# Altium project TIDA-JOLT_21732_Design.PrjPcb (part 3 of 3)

## Sheet JOLT_21732_Supply_Bias.SchDoc
size 431 x 279 mm; Date: Not shown in title block; ApprovedBy: Not shown in title block; CheckedBy: Not shown in title block; Author: Not shown in title block; CompanyName: Not shown in title block; DrawnBy: X.Gong; Engineer: Not shown in title block; Organization: Not shown in title block; Address1: Not shown in title block; Address2: Not shown in title block; Address3: Not shown in title block; Address4: Not shown in title block; DocumentNumber: 4; Revision: Use project parameter SCH_Rev; SheetNumber: 4; SheetTotal: 5; PageSetup: Record=PageOptions¦CenterHorizontal=True¦CenterVertical=True¦PrintScale=1.00¦XCorrection=1.00¦YCorrection=1.00¦PrintKind=0¦BorderSize=5000000¦LeftOffset=0¦BottomOffset=0¦Orientation=2¦PaperLength=1000¦PaperWidth=1000¦Scale=100¦PaperSource=15¦PrintQuality=600¦MediaType=1¦DitherType=10¦PaperKind=Letter¦PrintScaleMode=1
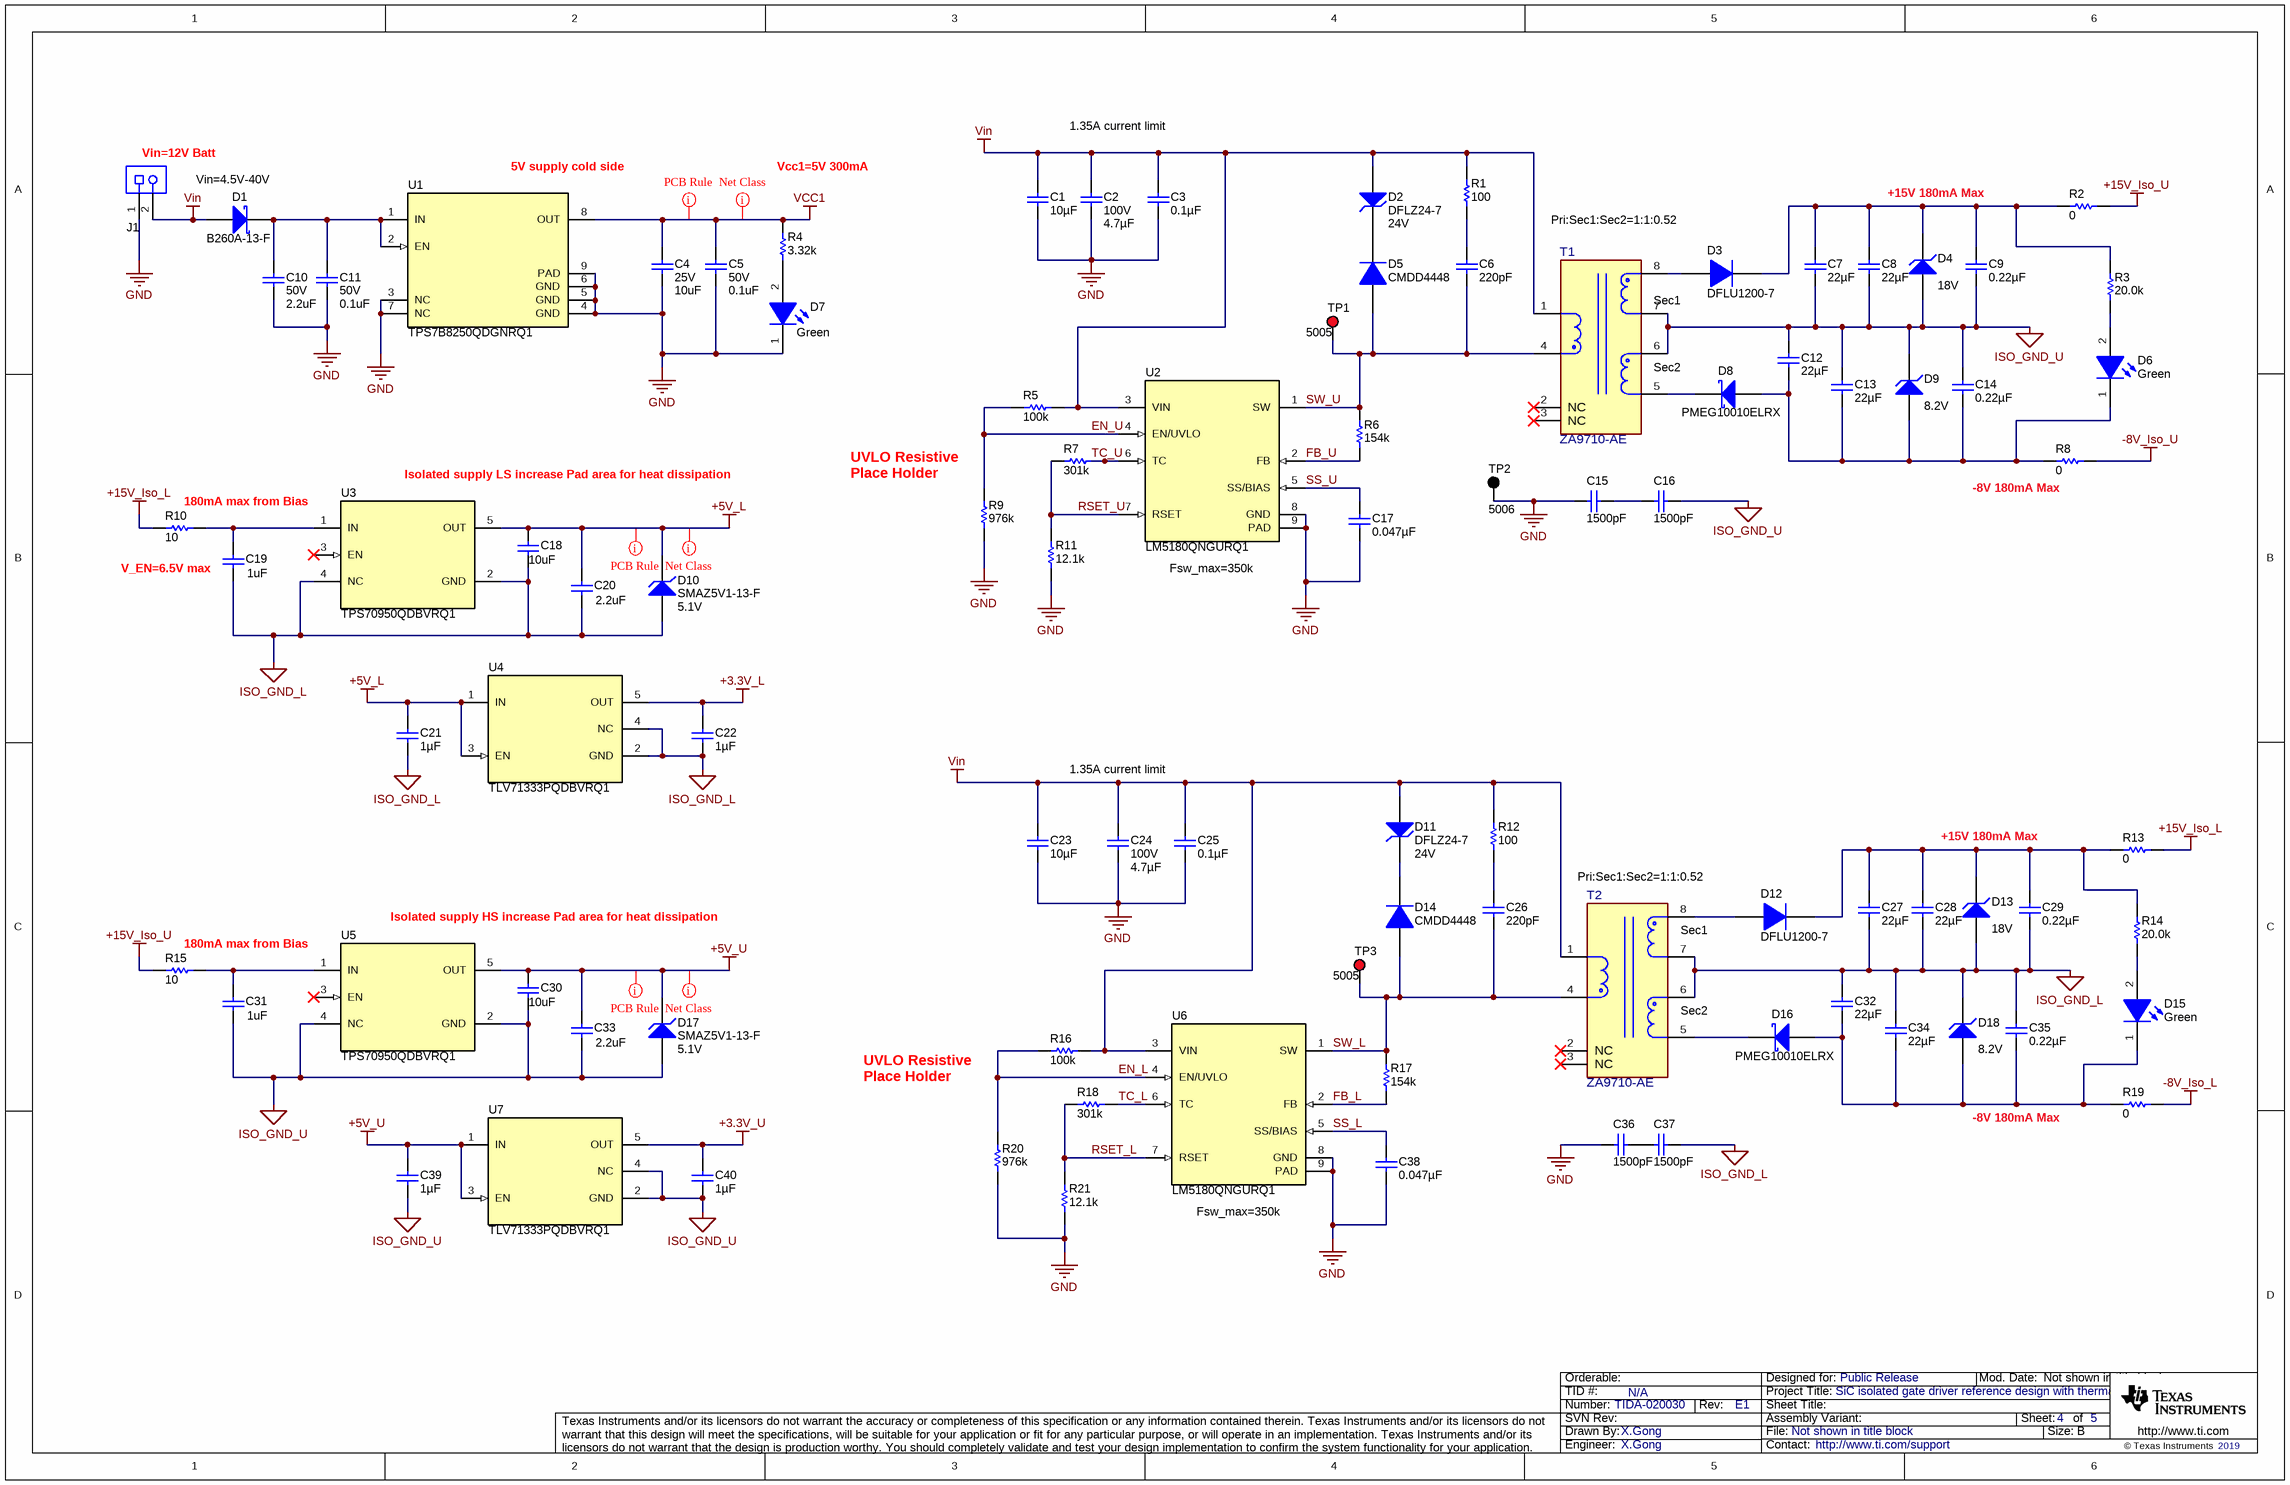
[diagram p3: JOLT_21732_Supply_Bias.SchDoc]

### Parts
C1  ValueDisplayed: 10µF  [2220_250]  (hidden comment: C5750X7S2A106K230KB)
C2  VDC_V: 100V  ValueDisplayed: 4.7µF  [1210_220]  (hidden comment: GCM32DC72A475KE02L)
C3  ValueDisplayed: 0.1µF  [0805_HV]  (hidden comment: GRM21BR72A104KAC4L)
C4  VDC_V: 25V  ValueDisplayed: 10uF  [1206_180]  (hidden comment: GRM31CR71E106KA12L)
C5  VDC_V: 50V  ValueDisplayed: 0.1uF  [0805_HV]  (hidden comment: GRM21BR71H104KA01L)
C6  ValueDisplayed: 220pF  [0603]  (hidden comment: GRM1885C2A221JA01D)
C7  ValueDisplayed: 22µF  [0805_HV]  (hidden comment: GRM21BR61E226ME44L)
C8  ValueDisplayed: 22µF  [0805_HV]  (hidden comment: GRM21BR61E226ME44L)
C9  ValueDisplayed: 0.22µF  [0805_HV]  (hidden comment: GRM21BR71H224KA01L)
C10  VDC_V: 50V  ValueDisplayed: 2.2uF  [1206_180]  (hidden comment: GRM31CR71H225KA88L)
C11  VDC_V: 50V  ValueDisplayed: 0.1uF  [0805_HV]  (hidden comment: GRM21BR71H104KA01L)
C12  ValueDisplayed: 22µF  [0805_HV]  (hidden comment: GRM21BR61E226ME44L)
C13  ValueDisplayed: 22µF  [0805_HV]  (hidden comment: GRM21BR61E226ME44L)
C14  ValueDisplayed: 0.22µF  [0805_HV]  (hidden comment: GRM21BR71H224KA01L)
C15  ValueDisplayed: 1500pF  [KY_700x500x1000]  (hidden comment: DE2E3KY152MN3AM02F)
C16  ValueDisplayed: 1500pF  [KY_700x500x1000]  (hidden comment: DE2E3KY152MN3AM02F)
C17  ValueDisplayed: 0.047µF  [0603]  (hidden comment: GRM188R71C473KA01D)
C18  ValueDisplayed: 10uF  [0805_HV]  (hidden comment: C2012X5R1E106K125AB)
C19  ValueDisplayed: 1uF  [0603]  (hidden comment: UMK107AB7105KA-T)
C20  ValueDisplayed: 2.2uF  [1206]  (hidden comment: C1206C225K4RACTU)
C21  ValueDisplayed: 1µF  [0603]  (hidden comment: GRM188R71E105KA12D)
C22  ValueDisplayed: 1µF  [0603]  (hidden comment: GRM188R71E105KA12D)
C23  ValueDisplayed: 10µF  [2220_250]  (hidden comment: C5750X7S2A106K230KB)
C24  VDC_V: 100V  ValueDisplayed: 4.7µF  [1210_220]  (hidden comment: GCM32DC72A475KE02L)
C25  ValueDisplayed: 0.1µF  [0805_HV]  (hidden comment: GRM21BR72A104KAC4L)
C26  ValueDisplayed: 220pF  [0603]  (hidden comment: GRM1885C2A221JA01D)
C27  ValueDisplayed: 22µF  [0805_HV]  (hidden comment: GRM21BR61E226ME44L)
C28  ValueDisplayed: 22µF  [0805_HV]  (hidden comment: GRM21BR61E226ME44L)
C29  ValueDisplayed: 0.22µF  [0805_HV]  (hidden comment: GRM21BR71H224KA01L)
C30  ValueDisplayed: 10uF  [0805_HV]  (hidden comment: C2012X5R1E106K125AB)
C31  ValueDisplayed: 1uF  [0603]  (hidden comment: UMK107AB7105KA-T)
C32  ValueDisplayed: 22µF  [0805_HV]  (hidden comment: GRM21BR61E226ME44L)
C33  ValueDisplayed: 2.2uF  [1206]  (hidden comment: C1206C225K4RACTU)
C34  ValueDisplayed: 22µF  [0805_HV]  (hidden comment: GRM21BR61E226ME44L)
C35  ValueDisplayed: 0.22µF  [0805_HV]  (hidden comment: GRM21BR71H224KA01L)
C36  ValueDisplayed: 1500pF  [KY_700x500x1000]  (hidden comment: DE2E3KY152MN3AM02F)
C37  ValueDisplayed: 1500pF  [KY_700x500x1000]  (hidden comment: DE2E3KY152MN3AM02F)
C38  ValueDisplayed: 0.047µF  [0603]  (hidden comment: GRM188R71C473KA01D)
C39  ValueDisplayed: 1µF  [0603]  (hidden comment: GRM188R71E105KA12D)
C40  ValueDisplayed: 1µF  [0603]  (hidden comment: GRM188R71E105KA12D)
D1  B260A-13-F  [SMA]
D2  DFLZ24-7  value 24V  [PowerDI123]
D3  DFLU1200-7  [PowerDI123]
D4  value 18V  [SOD-123]  (hidden comment: BZT52C18-7-F)
D5  CMDD4448  [SOD-323]
D6  value Green  [WL-SMCW_GREEN]  (hidden comment: 150060GS75000)
D7  value Green  [WL-SMCW_GREEN]  (hidden comment: 150060GS75000)
D8  PMEG10010ELRX  [SOD-123W]
D9  value 8.2V  [SOD-123]  (hidden comment: BZT52C8V2-7-F)
D10  SMAZ5V1-13-F  value 5.1V  [SMA]
D11  DFLZ24-7  value 24V  [PowerDI123]
D12  DFLU1200-7  [PowerDI123]
D13  value 18V  [SOD-123]  (hidden comment: BZT52C18-7-F)
D14  CMDD4448  [SOD-323]
D15  value Green  [WL-SMCW_GREEN]  (hidden comment: 150060GS75000)
D16  PMEG10010ELRX  [SOD-123W]
D17  SMAZ5V1-13-F  value 5.1V  [SMA]
D18  value 8.2V  [SOD-123]  (hidden comment: BZT52C8V2-7-F)
J1  OSTVN02A150  [On-Shore_OSTVN02A150]  (value not drawn)
R1  ValueDisplayed: 100  [0805_HV]  (hidden comment: CRCW0805100RFKEA)
R2  ValueDisplayed: 0  [0603]  (hidden comment: ERJ-3GEY0R00V)
R3  ValueDisplayed: 20.0k  [0805_HV]  (hidden comment: CRCW080520K0FKEA)
R4  ValueDisplayed: 3.32k  [0402]  (hidden comment: CRCW04023K32FKED)
R5  ValueDisplayed: 100k  [0805_HV]  (hidden comment: CRCW0805100KFKEA)
R6  ValueDisplayed: 154k  [0603]  (hidden comment: CRCW0603154KFKEA)
R7  ValueDisplayed: 301k  [0603]  (hidden comment: CRCW0603301KFKEA)
R8  ValueDisplayed: 0  [0603]  (hidden comment: ERJ-3GEY0R00V)
R9  ValueDisplayed: 976k  [0603]  (hidden comment: CRCW0603976KFKEA)
R10  ValueDisplayed: 10  [0805_HV]  (hidden comment: CRCW080510R0JNEA)
R11  ValueDisplayed: 12.1k  [0805_HV]  (hidden comment: CRCW080512K1FKEA)
R12  ValueDisplayed: 100  [0805_HV]  (hidden comment: CRCW0805100RFKEA)
R13  ValueDisplayed: 0  [0603]  (hidden comment: ERJ-3GEY0R00V)
R14  ValueDisplayed: 20.0k  [0805_HV]  (hidden comment: CRCW080520K0FKEA)
R15  ValueDisplayed: 10  [0805_HV]  (hidden comment: CRCW080510R0JNEA)
R16  ValueDisplayed: 100k  [0805_HV]  (hidden comment: CRCW0805100KFKEA)
R17  ValueDisplayed: 154k  [0603]  (hidden comment: CRCW0603154KFKEA)
R18  ValueDisplayed: 301k  [0603]  (hidden comment: CRCW0603301KFKEA)
R19  ValueDisplayed: 0  [0603]  (hidden comment: ERJ-3GEY0R00V)
R20  ValueDisplayed: 976k  [0603]  (hidden comment: CRCW0603976KFKEA)
R21  ValueDisplayed: 12.1k  [0805_HV]  (hidden comment: CRCW080512K1FKEA)
T1  ZA9710-AE  [FP-ZA9710-AE_SMT_8-MFG]
T2  ZA9710-AE  [FP-ZA9710-AE_SMT_8-MFG]
TP1  5005  [Keystone5005]
TP2  5006  [Keystone5006]
TP3  5005  [Keystone5005]
U1  TPS7B8250QDGNRQ1  [DGN0008D_N]
U2  LM5180QNGURQ1  [NGU0008C]
U3  TPS70950QDBVRQ1  [DBV0005A_N]
U4  TLV71333PQDBVRQ1  [DBV0005A_N]
U5  TPS70950QDBVRQ1  [DBV0005A_N]
U6  LM5180QNGURQ1  [NGU0008C]
U7  TLV71333PQDBVRQ1  [DBV0005A_N]

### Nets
+3.3V_L: C22.1 U4.5(OUT)
+3.3V_U: C40.1 U7.5(OUT)
+5V_L: C18.2 C20.1 C21.1 D10.1(K) U3.5(OUT) U4.1(IN) U4.3(EN)
+5V_U: C30.2 C33.1 C39.1 D17.1(K) U5.5(OUT) U7.1(IN) U7.3(EN)
+15V_Iso_L: R10.2 R13.2
+15V_Iso_U: R2.2 R15.2
-8V_Iso_L: R19.2
-8V_Iso_U: R8.2
GND: C1.2 C2.2 C3.2 C4.2 C5.2 C10.2 C11.2 C15.2 C17.2 C23.2 C24.2 C25.2 C36.2 C38.2 D7.1(K) J1.1 R9.1 R11.1 R20.1 R21.1 TP2.1 U1.3(NC) U1.4(GND) U1.5(GND) U1.6(GND) U1.7(NC) U1.9(PAD) U2.8(GND) U2.9(PAD) U6.8(GND) U6.9(PAD)
ISO_GND_L: C18.1 C19.2 C20.2 C21.2 C22.2 C27.2 C28.2 C29.2 C32.1 C34.1 C35.1 C37.1 D10.2(A) D13.2(A) D18.1(K) T2.6 T2.7 U3.2(GND) U3.4(NC) U4.2(GND) U4.4(NC)
ISO_GND_U: C7.2 C8.2 C9.2 C12.1 C13.1 C14.1 C16.1 C30.1 C31.2 C33.2 C39.2 C40.2 D4.2(A) D9.1(K) D17.2(A) T1.6 T1.7 U5.2(GND) U5.4(NC) U7.2(GND) U7.4(NC)
VCC1: C4.1 C5.1 R4.2 U1.8(OUT)
Vin: C1.1 C2.1 C3.1 C23.1 C24.1 C25.1 D1.2(A) D2.2(A) D11.2(A) J1.2 R1.2 R5.2 R12.2 R16.2 T1.1 T2.1 U2.3(VIN) U6.3(VIN)
EN_L: R16.1 R20.2 U6.4(EN/UVLO)
EN_U: R5.1 R9.2 U2.4(EN/UVLO)
FB_L: R17.1 U6.2(FB)
FB_U: R6.1 U2.2(FB)
RSET_L: R18.2 R21.2 U6.7(RSET)
RSET_U: R7.2 R11.2 U2.7(RSET)
SS_L: C38.1 U6.5(SS/BIAS)
SS_U: C17.1 U2.5(SS/BIAS)
SW_L: C26.2 D14.2(A) R17.2 T2.4 TP3.1 U6.1(SW)
SW_U: C6.2 D5.2(A) R6.2 T1.4 TP1.1 U2.1(SW)
TC_L: R18.1 U6.6(TC)
TC_U: R7.1 U2.6(TC)
NetC6_1: C6.1 R1.1
NetC7_1: C7.1 C8.1 C9.1 D3.1(K) D4.1(K) R2.1 R3.2
NetC10_1: C10.1 C11.1 D1.1(K) U1.1(IN) U1.2(EN)
NetC12_2: C12.2 C13.2 C14.2 D6.1(K) D8.2(A) D9.2(A) R8.1
NetC15_1: C15.1 C16.2
NetC19_1: C19.1 R10.1 U3.1(IN)
NetC26_1: C26.1 R12.1
NetC27_1: C27.1 C28.1 C29.1 D12.1(K) D13.1(K) R13.1 R14.2
NetC31_1: C31.1 R15.1 U5.1(IN)
NetC32_2: C32.2 C34.2 C35.2 D15.1(K) D16.2(A) D18.2(A) R19.1
NetC36_1: C36.1 C37.2
NetD2_1: D2.1(K) D5.1(K)
NetD3_2: D3.2(A) T1.8
NetD6_2: D6.2(A) R3.1
NetD7_2: D7.2(A) R4.1
NetD8_1: D8.1(K) T1.5
NetD11_1: D11.1(K) D14.1(K)
NetD12_2: D12.2(A) T2.8
NetD15_2: D15.2(A) R14.1
NetD16_1: D16.1(K) T2.5

Not connected (* = marked no-connect by the designer): T1 2(NC)* 3(NC)*; T2 2(NC)* 3(NC)*; U3 3(EN)*; U5 3(EN)*

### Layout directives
rule Width Constraint [Pref Width = 80mil    Min Width = 20mil    Max Width = 120mil]: +5V_L, +5V_U, VCC1
net class PowerNets: +5V_L, +5V_U, VCC1

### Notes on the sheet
- (near J1) Vin=12V Batt
- (near U1) 5V supply cold side
- Vcc1=5V 300mA
- 1.35A current limit
- Vin=4.5V-40V
- Pri:Sec1:Sec2=1:1:0.52
- +15V 180mA Max
- (near T1) Sec1
- (near T1) Sec2
- (near R10) 180mA max from Bias
- Isolated supply LS increase Pad area for heat dissipation
- (near R9) UVLO Resistive Place Holder
- (near R8) -8V 180mA Max
- V_EN=6.5V max
- (near U2) Fsw_max=350k
- (near T2) Pri:Sec1:Sec2=1:1:0.52
- (near R15) 180mA max from Bias
- Isolated supply HS increase Pad area for heat dissipation
- (near T2) Sec1
- (near T2) Sec2
- UVLO Resistive Place Holder
- -8V 180mA Max
- (near U6) Fsw_max=350k

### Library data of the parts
C1 C23 = C5750X7S2A106K230KB: CAP, CERM, 10 µF, 100 V,+/- 10%, X7S, 2220; Manufacturer: TDK; Polarized: N; CompType: Capacitor; Value: 10uF; U/M: EA; Cap_F: 0.00001; Tolerance_%: 10; ESR_ohm: 0.003179; Value1: 0.003179 ohm; VDC_V: 100; Value2: 100V; IRMS_A: 5.11992; TaMin_C: -55; TaMax_C: 125; Cap_Case: 2220; SizeArea_mm2: 28.5; SizeAreaWB_mm2: 53.9; SizeX_mm: 5.7; SizeY_mm: 5; SizeZ_mm: 2.5; AEC Category: Q200
C2 C24 = CMP-0082268-1: CAP, CERM, 4.7 µF, 100 V,+/- 10%, X7S, AEC-Q200 Grade 1, 1210; Manufacturer: MuRata; TaMin_C: -55°C; ESR_ohm: 1m; Polarized: N; SizeAreaWB_mm2: 14.7; Value1: 0.001 ohm; U/M: EA; Value: 4.7uF; TaMax_C: 125°C; SizeZ_mm: 2.2; SizeX_mm: 3.2; SizeY_mm: 2.5; Cap_Case: 1210; SizeArea_mm2: 8; AEC Qualified: Y; IRMS_A: 6A; AEC Grade: 1; AEC Category: Q200
C3 C25 = GRM21BR72A104KAC4L: CAP, CERM, 0.1 µF, 100 V,+/- 10%, X7R, 0805; Manufacturer: MuRata; Polarized: N; CompType: Capacitor; Value: 0.1uF; U/M: EA; Cap_F: 0.0000001; Tolerance_%: 10; VDC_V: 100; Value2: 100V; TaMin_C: -55; TaMax_C: 125; Cap_Case: 0805; SizeArea_mm2: 2.5; SizeAreaWB_mm2: 6.75; SizeX_mm: 2; SizeY_mm: 1.25; SizeZ_mm: 1.45; AEC Category: Q200
C4 = CMP-0008965-2: CAP, CERM, 10 uF, 25 V, +/- 10%, X7R, 1206; Manufacturer: MuRata; TaMin_C: -55°C; Polarized: N; SizeAreaWB_mm2: 10.92; Value1: Unknown; U/M: EA; Value: 10uF; TaMax_C: 125°C; SizeZ_mm: 1.8; SizeX_mm: 3.2; SizeY_mm: 1.6; Cap_Case: 2220; SizeArea_mm2: 5.12; Cap_F: 10µF; AEC Category: Q200
C5 C11 = CMP-0008349-2: CAP, CERM, 0.1 uF, 50 V, +/- 10%, X7R, 0805; Manufacturer: MuRata; TaMin_C: -55°C; Polarized: N; SizeAreaWB_mm2: 6.75; Value1: Unknown; U/M: EA; Value: 0.1uF; TaMax_C: 125°C; SizeZ_mm: 1.45; SizeX_mm: 2; SizeY_mm: 1.25; Cap_Case: 0805; SizeArea_mm2: 2.5; Cap_F: 100nF; AEC Category: Q200
C6 C26 = GRM1885C2A221JA01D: CAP, CERM, 220 pF, 100 V,+/- 5%, C0G/NP0, 0603; Manufacturer: MuRata; Polarized: N; CompType: Capacitor; Value: 220pF; U/M: EA; Cap_F: 0.00000000022; Tolerance_%: 5; VDC_V: 100; Value2: 100V; TaMin_C: -55; TaMax_C: 125; SizeArea_mm2: 1.28; SizeAreaWB_mm2: 4.68; SizeX_mm: 1.6; SizeY_mm: 0.8; SizeZ_mm: 1; AEC Category: Q200
C7 C8 C12 C13 C27 C28 C32 C34 = GRM21BR61E226ME44L: CAP, CERM, 22 µF, 25 V,+/- 20%, X5R, 0805; Manufacturer: MuRata; Polarized: N; CompType: Capacitor; Value: 22uF; U/M: EA; Cap_F: 0.000022; Tolerance_%: 20; VDC_V: 25; Value2: 25V; TaMin_C: -55; TaMax_C: 85; Cap_Case: 0805; SizeArea_mm2: 2.5; SizeAreaWB_mm2: 6.75; SizeX_mm: 2; SizeY_mm: 1.25; SizeZ_mm: 1.45; AEC Category: Q200; Green_Lifecycle: Active; Green_REACh: Passed
C9 C14 C29 C35 = GRM21BR71H224KA01L: CAP, CERM, 0.22 µF, 50 V,+/- 10%, X7R, 0805; Manufacturer: MuRata; Polarized: N; CompType: Capacitor; Value: 0.22uF; U/M: EA; Cap_F: 0.00000022; Tolerance_%: 10; VDC_V: 50; Value2: 50V; TaMin_C: -55; TaMax_C: 125; Cap_Case: 0805; SizeArea_mm2: 2.5; SizeAreaWB_mm2: 6.75; SizeX_mm: 2; SizeY_mm: 1.25; SizeZ_mm: 1.45; AEC Category: Q200; Green_Lifecycle: Active; Green_REACh: Passed
C10 = CMP-0008968-2: CAP, CERM, 2.2 uF, 50 V, +/- 10%, X7R, 1206; Manufacturer: MuRata; TaMin_C: -55°C; Polarized: N; SizeAreaWB_mm2: 10.92; Value1: Unknown; U/M: EA; Value: 2.2uF; TaMax_C: 125°C; SizeZ_mm: 1.8; SizeX_mm: 3.2; SizeY_mm: 1.6; Cap_Case: 1206; SizeArea_mm2: 5.12; Cap_F: 2.2µF; AEC Category: Q200
C15 C16 C36 C37 = CMP-0009609-4: CAP, CERM, 1500 pF, X1 250 VAC/Y2 300 VAC, +/- 20%, E, TH; Manufacturer: MuRata; TaMin_C: -25°C; Polarized: N; SizeAreaWB_mm2: 66.5; Value1: Unknown; U/M: EA; Value: 1500pF; TaMax_C: 85°C; SizeZ_mm: 10; SizeX_mm: 7.5; SizeY_mm: 5; Cap_Case: 7x5x10mm; SizeArea_mm2: 37.5; Cap_F: 1.5nF; AEC Category: Q200; AC_Safety: X1Y2; VAC_X: 250V; VAC_Y: 300V
C17 C38 = GRM188R71C473KA01D: CAP, CERM, 0.047 µF, 16 V,+/- 10%, X7R, 0603; Manufacturer: MuRata; Polarized: N; CompType: Capacitor; Value: 0.047uF; U/M: EA; Cap_F: 0.000000047; Tolerance_%: 10; VDC_V: 16; Value2: 16V; TaMin_C: -55; TaMax_C: 125; SizeArea_mm2: 1.28; SizeAreaWB_mm2: 4.68; SizeX_mm: 1.6; SizeY_mm: 0.8; SizeZ_mm: 1; AEC Category: Q200; Green_Lifecycle: Active; Green_REACh: Passed
C18 C30 = CMP-0007828-2: CAP, CERM, 10 uF, 25 V, +/- 10%, X5R, 0805; Manufacturer: TDK; TaMin_C: -55°C; Polarized: N; SizeAreaWB_mm2: 6.75; Value1: Unknown; U/M: EA; Value: 10uF; TaMax_C: 85°C; SizeZ_mm: 1.45; SizeX_mm: 2; SizeY_mm: 1.25; Cap_Case: 0805; Value2: 25V; SizeArea_mm2: 2.5; CompType: Capacitor; Cap_F: 10µF; AEC Category: Q200
C19 C31 = CMP-0007508-5: CAP, CERM, 1 uF, 50 V, +/- 10%, X7R, 0603; Manufacturer: Taiyo Yuden; TaMin_C: -55°C; Polarized: N; SizeAreaWB_mm2: 4.68; Value1: Unknown; U/M: EA; Value: 1uF; TaMax_C: 125°C; SizeZ_mm: 1; SizeX_mm: 1.6; SizeY_mm: 0.8; Value2: 50V; SizeArea_mm2: 1.28; CompType: Capacitor; Cap_F: 1µF; AEC Category: Q200
C20 C33 = CMP-0008606-2: CAP, CERM, 2.2 uF, 16 V, +/- 10%, X7R, 1206; Manufacturer: Kemet; TaMin_C: -55°C; ESR_ohm: 9m; Polarized: N; SizeAreaWB_mm2: 10.92; Value1: 0.009 ohm; U/M: EA; Value: 2.2uF; TaMax_C: 125°C; SizeZ_mm: 1.35; SizeX_mm: 3.2; SizeY_mm: 1.6; Value2: 16V; SizeArea_mm2: 5.12; CompType: Capacitor; Cap_F: 2.2µF; IRMS_A: 4.46A; AEC Category: Q200
C21 C22 C39 C40 = GRM188R71E105KA12D: CAP, CERM, 1 µF, 25 V,+/- 10%, X7R, 0603; Manufacturer: MuRata; Polarized: N; CompType: Capacitor; Value: 1uF; U/M: EA; Cap_F: 0.000001; Tolerance_%: 10; VDC_V: 25; Value2: 25V; TaMin_C: -55; TaMax_C: 125; SizeArea_mm2: 1.28; SizeAreaWB_mm2: 4.68; SizeX_mm: 1.6; SizeY_mm: 0.8; SizeZ_mm: 1; AEC Category: Q200; Green_Lifecycle: Active; Green_REACh: Passed
D1 = CMP-0028407-1: Diode, Schottky, 60 V, 2 A, SMA; Manufacturer: Diodes Inc.; Io_A: 2A; Green_Lifecycle: Active; SizeAreaWB_mm2: 37.3428; Vr_V: 60V; Green_REACh: Passed; TJmax_C: 150°C; U/M: EA; Value: 60V; SizeZ_mm: 2.87; SizeX_mm: 5.59; SizeY_mm: 2.92; Vf_V: 7dV; Value2: 0.7V; SizeArea_mm2: 16.3228; AEC Category: Q101; RJC_CperW: 20
D2 D11 = CMP-0005415-2: Diode, Zener, 24 V, 1 W, PowerDI123; Manufacturer: Diodes Inc.; Power_W: 1W; SizeAreaWB_mm2: 13.066; RJA_CperW: 110; U/M: EA; SizeZ_mm: 0.98; SizeX_mm: 3.7; SizeY_mm: 1.78; SizeArea_mm2: 6.586; AEC Category: Q101
D3 D12 = CMP-0077072-1: Diode, Superfast Rectifier, 200 V, 1 A, AEC-Q101, PowerDI123; Manufacturer: Diodes Inc.; SizeAreaWB_mm2: 13.066; Vr_V: 200V; SizeArea_mm2: 6.586; AEC Qualified: Y; TJmax_C: 150°C; AEC Category: Q101; Value: 200V; SizeZ_mm: 0.98; Green_REACh: Incomplete; Io_A: 1A; Vf_V: 9.8dV; SizeY_mm: 1.78; Value2: 0.98V; Green_Lifecycle: Not Set; U/M: EA; SizeX_mm: 3.7
D4 D13 = CMP-0084402-1: Diode, Zener, 18 V, 500 mW, AEC-Q101, SOD-123; Manufacturer: Diodes Inc.; AEC Category: Q101; Value1: 0.5W; SizeArea_mm2: 6.545; AEC Qualified: Y; Green_Lifecycle: Active; Power_W: 500mW; SizeZ_mm: 1.35; Green_REACh: Incomplete; SizeY_mm: 1.7; SizeAreaWB_mm2: 13.095; SizeX_mm: 3.85; RJA_CperW: 338
D5 D14 = CMP-0029019-1: Diode, Ultrafast, 75 V, 0.25 A, SOD-323; Manufacturer: Central Semiconductor; Io_A: 2.5dA; Green_Lifecycle: Not Set; SizeAreaWB_mm2: 8.695; Vr_V: 75V; Green_REACh: Incomplete; Value1: 0.25A; TJmax_C: 175°C; U/M: EA; Value: 75V; SizeZ_mm: 1; SizeX_mm: 2.7; SizeY_mm: 1.35; Vf_V: 1.2V; SizeArea_mm2: 3.645; AEC Category: Q101
D6 D7 D15 = CMP-0002905-1: LED, Green, SMD; Manufacturer: Wurth Elektronik; Io_A: 20mA; Tjmax_C: 85°C; Value1: W; U/M: EA; Angle: 140; Vf_V: 3.2V; Type: InGaN
D8 D16 = CMP-0028782-1: Diode, Schottky, 100 V, 1 A, AEC-Q101, SOD-123W; Manufacturer: Nexperia; Io_A: 1A; Green_Lifecycle: Not Set; SizeAreaWB_mm2: 12.15; Vr_V: 100V; Green_REACh: Incomplete; TJmax_C: 175°C; U/M: EA; Value: 100V; SizeZ_mm: 1; SizeX_mm: 3.5; SizeY_mm: 1.7; Vf_V: 7.7dV; Value2: 0.77V; SizeArea_mm2: 5.95; AEC Qualified: Y; AEC Category: Q101
D9 D18 = CMP-0005813-1: Diode, Zener, 8.2 V, 500 mW, SOD-123; Manufacturer: Diodes Inc.; Power_W: 500mW; SizeAreaWB_mm2: 13.095; Value1: 0.5W; RJA_CperW: 338; U/M: EA; SizeZ_mm: 1.35; SizeX_mm: 3.85; SizeY_mm: 1.7; SizeArea_mm2: 6.545; AEC Category: Q101
D10 D17 = CMP-0005529-3: Diode, Zener, 5.1 V, 1 W, SMA; Manufacturer: Diodes Inc.; RJA_CperW: 125; SizeArea_mm2: 16.3228; AEC Category: Q101; SizeX_mm: 5.59; Value1: 1W; SizeZ_mm: 2.87; SizeAreaWB_mm2: 37.3428; SizeY_mm: 2.92
J1 = CMP-0075076-1: Terminal Block, 2.54mm, 2x1, Brass, TH; Manufacturer: On-Shore Technology; CT: True; Green_REACh: Incomplete; CNHeader: False; Green_Lifecycle: Not Set
R1 R12 = CRCW0805100RFKEA: RES, 100, 1%, 0.125 W, 0805; Manufacturer: Vishay-Dale; CompType: Resistor; Value: 100; Value_Code: 100R; Tolerance_%: 1; Power_W: 0.125; Value2: 0.125W; VDC_V: 150; TempCo: 100 ppm/C; SizeArea_mm2: 2.5; SizeX_mm: 2; SizeY_mm: 1.25; SizeZ_mm: 1.45; EIA_Code: E96; U/M: EA; AEC Category: Q200; Green_Lifecycle: Active; Green_REACh: Passed
R2 R8 R13 R19 = CMP-0025874-3: RES, 0, 5%, 0.1 W, 0603; Manufacturer: Panasonic; Power_W: 100mW; TempCo: 600 ppm/C; Value_Code: 0000; U/M: EA; Value: 0; EIA_Code: E24; SizeX_mm: 1.6; SizeY_mm: 0.8; SizeZ_mm: 1; Value2: 0.1W; SizeArea_mm2: 1.28; VDC_V: 50V; AEC Category: Q200
R3 R14 = CRCW080520K0FKEA: RES, 20.0 k, 1%, 0.125 W, 0805; Manufacturer: Vishay-Dale; CompType: Resistor; Value: 20.0k; Res_ohm: 20000; Value_Code: 20k0; Tolerance_%: 1; Power_W: 0.125; Value2: 0.125W; VDC_V: 150; TempCo: 100 ppm/C; SizeArea_mm2: 2.5; SizeX_mm: 2; SizeY_mm: 1.25; SizeZ_mm: 1.45; EIA_Code: E96; U/M: EA; AEC Category: Q200; Green_Lifecycle: Active; Green_REACh: Passed
R4 = CRCW04023K32FKED: RES, 3.32 k, 1%, 0.063 W, 0402; Manufacturer: Vishay-Dale; CompType: Resistor; Value: 3.32k; Res_ohm: 3320; Value_Code: 3k32; Tolerance_%: 1; Power_W: 0.063; Value2: 0.063W; VDC_V: 50; TempCo: 100 ppm/C; SizeArea_mm2: 0.5; SizeZ_mm: 0.6; EIA_Code: E96; U/M: EA; AEC Category: Q200; Green_Lifecycle: Active; Green_REACh: Passed
R5 R16 = CRCW0805100KFKEA: RES, 100 k, 1%, 0.125 W, 0805; Manufacturer: Vishay-Dale; CompType: Resistor; Value: 100k; Res_ohm: 100000; Tolerance_%: 1; Power_W: 0.125; Value2: 0.125W; VDC_V: 150; TempCo: 100 ppm/C; SizeArea_mm2: 2.5; SizeX_mm: 2; SizeY_mm: 1.25; SizeZ_mm: 1.45; EIA_Code: E96; U/M: EA; AEC Category: Q200; Green_Lifecycle: Active; Green_REACh: Passed
R6 R17 = CRCW0603154KFKEA: RES, 154 k, 1%, 0.1 W, 0603; Manufacturer: Vishay-Dale; CompType: Resistor; Value: 154k; Res_ohm: 154000; Tolerance_%: 1; Power_W: 0.1; Value2: 0.1W; VDC_V: 75; TempCo: 100 ppm/C; SizeArea_mm2: 1.28; SizeX_mm: 1.6; SizeY_mm: 0.8; EIA_Code: E96; U/M: EA; AEC Category: Q200; Green_Lifecycle: Active; Green_REACh: Passed
R7 R18 = CRCW0603301KFKEA: RES, 301 k, 1%, 0.1 W, 0603; Manufacturer: Vishay-Dale; CompType: Resistor; Value: 301k; Res_ohm: 301000; Tolerance_%: 1; Power_W: 0.1; Value2: 0.1W; VDC_V: 75; TempCo: 100 ppm/C; SizeArea_mm2: 1.28; SizeX_mm: 1.6; SizeY_mm: 0.8; EIA_Code: E96; U/M: EA; AEC Category: Q200; Green_Lifecycle: Active; Green_REACh: Passed
R9 R20 = CRCW0603976KFKEA: RES, 976 k, 1%, 0.1 W, 0603; Manufacturer: Vishay-Dale; CompType: Resistor; Value: 976k; Res_ohm: 976000; Tolerance_%: 1; Power_W: 0.1; Value2: 0.1W; VDC_V: 75; TempCo: 100 ppm/C; SizeArea_mm2: 1.28; SizeX_mm: 1.6; SizeY_mm: 0.8; EIA_Code: E96; U/M: EA; AEC Category: Q200
R10 R15 = CMP-0020448-2: RES, 10, 5%, 0.125 W, 0805; Manufacturer: Vishay-Dale; Power_W: 125mW; TempCo: 200 ppm/C; Value_Code: 10R0; U/M: EA; Value: 10; EIA_Code: E24; SizeX_mm: 2; SizeY_mm: 1.25; SizeZ_mm: 1.45; Value2: 0.125W; SizeArea_mm2: 2.5; VDC_V: 150V; AEC Category: Q200
R11 R21 = CRCW080512K1FKEA: RES, 12.1 k, 1%, 0.125 W, 0805; Manufacturer: Vishay-Dale; CompType: Resistor; Value: 12.1k; Res_ohm: 12100; Value_Code: 12k1; Tolerance_%: 1; Power_W: 0.125; Value2: 0.125W; VDC_V: 150; TempCo: 100 ppm/C; SizeArea_mm2: 2.5; SizeX_mm: 2; SizeY_mm: 1.25; SizeZ_mm: 1.45; EIA_Code: E96; U/M: EA; AEC Category: Q200; Green_Lifecycle: Active; Green_REACh: Passed
T1 T2 = CMP-0087757-1: Flyback Transformer; Manufacturer: Coilcraft; Ind_H: 27µH; SizeZ_mm: 10mm; DCR_ohm: 0.169; AEC Qualified: No
TP1 TP3 = CMP-0055142-1: Test Point, Compact, Red, TH; Manufacturer: Keystone; CNHeader: FALSE; Green_Lifecycle: Active; Green_REACh: Passed; ContactFinish: Silver; CT: TRUE
TP2 = CMP-0055143-1: Test Point, Compact, Black, TH; Manufacturer: Keystone; CNHeader: FALSE; Green_Lifecycle: Active; Green_REACh: Passed; ContactFinish: Silver; CT: TRUE
U1 = CMP-0013313-4: 300mA High-Voltage Ultra-Low-Iq Low-Dropout (LDO) Regulator, DGN0008D (VSSOP-8); Manufacturer: Texas Instruments; SizeX_mm: 5.05; SizeY_mm: 3.1; CompType: IC; SizeZ_mm: 1.1; SizeArea_mm2: 15.655; SizeAreaWB_mm2: 35.955; AEC Category: Q200; AEC Qualified: Y
U2 U6 = CMP-0078633-2: 70-V PSR Flyback Converter With 100-V, 1.2-A Power Switch and Ultra-Low IQ, NGU0008C (WSON-8); Alternate PartNumber: LM5180QNGUTQ1; Alternate Manufacturer: Texas Instruments; SizeAreaWB_mm2: 25; SizeZ_mm: 0.8; SizeX_mm: 4; SizeArea_mm2: 16; CompType: IC; AEC Qualified: Y; AEC Category: Q200
U3 U5 = CMP-0079136-1: 150-mA, 30-V, Ultra-Low IQ, Wide Input LDO with Reverse Current Protection for Automotive, DBV0005A (SOT-23-5); Alternate Manufacturer: Texas Instruments; SizeAreaWB_mm2: 14.82; SizeZ_mm: 1.45; SizeX_mm: 2.8; SizeY_mm: 2.9; SizeArea_mm2: 8.12; CompType: IC; AEC Qualified: Y; AEC Category: Q200
U4 U7 = CMP-0073750-1: Capacitor-Free, 150-mA, LDO Regulator w/ Foldback Current Limit, DBV0005A (SOT-23-5); Alternate Manufacturer: Texas Instruments; SizeAreaWB_mm2: 14.82; U/M: EA; SizeZ_mm: 1.45; SizeX_mm: 2.8; SizeY_mm: 2.9; SizeArea_mm2: 8.12; CompType: IC

## Sheet JOLT_21732_Design_EVM_Hardware.SchDoc
size 431 x 279 mm; Date: Not shown in title block; ApprovedBy: Not shown in title block; CheckedBy: Not shown in title block; Author: Not shown in title block; CompanyName: Not shown in title block; Engineer: Not shown in title block; Organization: Not shown in title block; Address1: Not shown in title block; Address2: Not shown in title block; Address3: Not shown in title block; Address4: Not shown in title block; DocumentNumber: 5; Revision: Use project parameter SCH_Rev; SheetNumber: 5; SheetTotal: 5; PageSetup: Record=PageOptions¦CenterHorizontal=True¦CenterVertical=True¦PrintScale=1.00¦XCorrection=1.00¦YCorrection=1.00¦PrintKind=0¦BorderSize=5000000¦LeftOffset=0¦BottomOffset=0¦Orientation=2¦PaperLength=1000¦PaperWidth=1000¦Scale=100¦PaperSource=15¦PrintQuality=600¦MediaType=1¦DitherType=10¦PaperKind=Letter¦PrintScaleMode=1
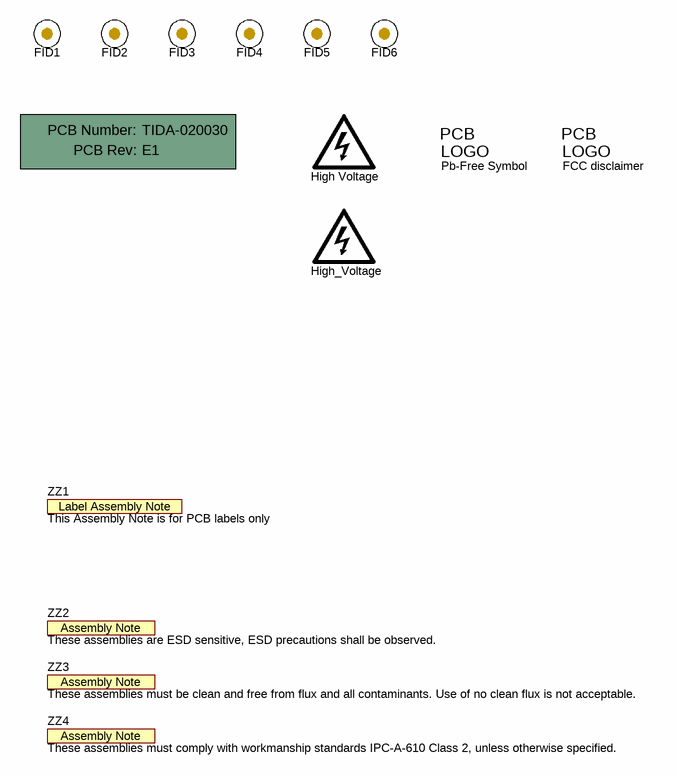
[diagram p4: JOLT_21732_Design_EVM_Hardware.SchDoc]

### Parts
!PCB1  Printed Circuit Board  (value not drawn)  (mechanical)
FID1  Fiducial  [Fiducial10-20]  (value not drawn)
FID2  Fiducial  [Fiducial10-20]  (value not drawn)
FID3  Fiducial  [Fiducial10-20]  (value not drawn)
FID4  Fiducial  [Fiducial10-20]  (value not drawn)
FID5  Fiducial  [Fiducial10-20]  (value not drawn)
FID6  Fiducial  [Fiducial10-20]  (value not drawn)
High_Voltage  DANGER HIGH VOLTAGE  [IEC_HighVoltage_Small]  (value not drawn)  (no BOM)
High_Voltage  DANGER HIGH VOLTAGE  [IEC_HighVoltage_Small]  (value not drawn)  (no BOM)
Logo1  Pb-Free Symbol  [Pb-Free_Overlay_Small]  (no BOM)
Logo2  FCC disclaimer  [FCC_disclaimer]  (no BOM)
ZZ1  This Assembly Note is for PCB labels only  [AssemblyNoteLabel]  (no BOM)
ZZ2  These assemblies are ESD sensitive, ESD precautions shall be observed.  [AssemblyNote]  (no BOM)
ZZ3  These assemblies must be clean and free from flux and all contaminants. Use of no clean flux is not acceptable.  [AssemblyNote]  (no BOM)
ZZ4  These assemblies must comply with workmanship standards IPC-A-610 Class 2, unless otherwise specified.  [AssemblyNote]  (no BOM)

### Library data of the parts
!PCB1 = CMP-0003618-2: Manufacturer: Any; PartNumber: TIDA-020030
FID1-FID6 = CMP-0077181-1: Fiducial mark.  There is nothing to buy or mount.
High_Voltage High_Voltage = IEC_HighVoltage: IEC 61010-1 High Voltage Warning; SymbolCreator: a0412235
Logo1 = CMP-0074839-1: SymbolCreator: a0412235; Library Reference: Logo
Logo2 = CMP-0074847-1: FCC_disclaimer; Library Reference: Logo
ZZ1 = CMP-0003616-3
ZZ2 = CMP-0077236-1
ZZ3 = CMP-0077237-1
ZZ4 = CMP-0077238-1

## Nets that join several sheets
0VInj_AIN_L: JOLT_21732_Driver_Conn (J2.3), JOLT_21732_OI_AIN_PWM_check (R151.1 R169.1 S6.2)
5VInj_AIN_L: JOLT_21732_Driver_Conn (J2.8), JOLT_21732_OI_AIN_PWM_check (R145.1 R156.1 S5.2)
5VInj_AIN_U: JOLT_21732_Driver_Conn (J3.7), JOLT_21732_OI_AIN_PWM_check (R120.1 R133.1 S2.2)
15V_Fault_U: JOLT_21732_OI_AIN_PWM_check (U21.10), JOLT_21732_DCbus_Thermal_LS (R53.2 R170.2)
15V_Monitor_L: JOLT_21732_Driver_Conn (J4.6), JOLT_21732_DCbus_Thermal_LS (U10.6)
15V_Monitor_U: JOLT_21732_Driver_Conn (J3.3), JOLT_21732_OI_AIN_PWM_check (U21.7)
+3.3V_L: JOLT_21732_DCbus_Thermal_LS (7 pins), JOLT_21732_Supply_Bias (C22.1 U4.5)
+5V_L: JOLT_21732_OI_AIN_PWM_check (13 pins), JOLT_21732_DCbus_Thermal_LS (C42.1 C45.2 U8.1), JOLT_21732_Supply_Bias (7 pins)
+5V_U: JOLT_21732_OI_AIN_PWM_check (13 pins), JOLT_21732_Supply_Bias (7 pins)
+15V_Iso_L: JOLT_21732_Driver_Conn (8 pins), JOLT_21732_OI_AIN_PWM_check (C138.1 Q14.2 R152.2), JOLT_21732_DCbus_Thermal_LS (5 pins), JOLT_21732_Supply_Bias (R10.2 R13.2)
+15V_Iso_U: JOLT_21732_Driver_Conn (6 pins), JOLT_21732_OI_AIN_PWM_check (C137.1 Q8.2 R127.2), JOLT_21732_DCbus_Thermal_LS (5 pins), JOLT_21732_Supply_Bias (R2.2 R15.2)
-8V_Iso_L: JOLT_21732_Driver_Conn (7 pins), JOLT_21732_Supply_Bias (R19.2)
-8V_Iso_U: JOLT_21732_Driver_Conn (7 pins), JOLT_21732_Supply_Bias (R8.2)
AIN_L: JOLT_21732_Driver_Conn (C98.1 D30.1 R101.2 U15.1), JOLT_21732_OI_AIN_PWM_check (D38.2 Q13.3 R158.2)
AIN_U: JOLT_21732_Driver_Conn (C87.1 D25.1 R72.2 U14.1), JOLT_21732_OI_AIN_PWM_check (D32.2 Q7.3 R135.2)
BUSIN_N: JOLT_21732_Driver_Conn (C98.2), JOLT_21732_DCbus_Thermal_LS (R31.1 R34.2 R41.2)
BUSIN_P: JOLT_21732_Driver_Conn (R101.1), JOLT_21732_DCbus_Thermal_LS (R22.1 R28.2)
CS_temp_L: JOLT_21732_Driver_Conn (J4.4), JOLT_21732_DCbus_Thermal_LS (U10.4)
DU: JOLT_21732_Driver_Conn (MD1.14), JOLT_21732_DCbus_Thermal_LS (R27.2)
Gate_L: JOLT_21732_Driver_Conn (12 pins), JOLT_21732_OI_AIN_PWM_check (R148.2)
Gate_U: JOLT_21732_Driver_Conn (12 pins), JOLT_21732_OI_AIN_PWM_check (R122.2)
GND: JOLT_21732_Driver_Conn (24 pins), JOLT_21732_OI_AIN_PWM_check (30 pins), JOLT_21732_DCbus_Thermal_LS (10 pins), JOLT_21732_Supply_Bias (31 pins)
ISO_GND_L: JOLT_21732_Driver_Conn (13 pins), JOLT_21732_OI_AIN_PWM_check (24 pins), JOLT_21732_DCbus_Thermal_LS (20 pins), JOLT_21732_Supply_Bias (21 pins)
ISO_GND_U: JOLT_21732_Driver_Conn (14 pins), JOLT_21732_OI_AIN_PWM_check (23 pins), JOLT_21732_DCbus_Thermal_LS (6 pins), JOLT_21732_Supply_Bias (21 pins)
OC_L: JOLT_21732_Driver_Conn (MD1.7 R84.2 R100.2), JOLT_21732_OI_AIN_PWM_check (R160.1 R165.1)
OC_U: JOLT_21732_Driver_Conn (MD1.12 R73.2 R74.2), JOLT_21732_OI_AIN_PWM_check (R137.1 R140.1)
OI_Inj_OI_L: JOLT_21732_Driver_Conn (J2.1), JOLT_21732_OI_AIN_PWM_check (R143.1 R159.1 S4.2)
OI_Inj_OI_U: JOLT_21732_Driver_Conn (J3.5), JOLT_21732_OI_AIN_PWM_check (R118.1 R136.1 S1.2)
PWM_Low_Inj_L: JOLT_21732_Driver_Conn (J2.5), JOLT_21732_OI_AIN_PWM_check (U22.5)
PWM_Low_Inj_U: JOLT_21732_Driver_Conn (J3.8), JOLT_21732_OI_AIN_PWM_check (U21.5)
PWM_out_L: JOLT_21732_Driver_Conn (J2.6), JOLT_21732_OI_AIN_PWM_check (R113.2 U22.6)
PWM_out_U: JOLT_21732_Driver_Conn (J3.6), JOLT_21732_OI_AIN_PWM_check (R111.2 U21.6)
SCLK_temp_L: JOLT_21732_Driver_Conn (J4.3), JOLT_21732_DCbus_Thermal_LS (U10.3)
SDO_temp_L: JOLT_21732_Driver_Conn (J4.5), JOLT_21732_DCbus_Thermal_LS (U10.5)
T_L+: JOLT_21732_Driver_Conn (MD1.4 R171.1), JOLT_21732_DCbus_Thermal_LS (R43.1)
T_L-: JOLT_21732_Driver_Conn (MD1.5 R82.2), JOLT_21732_DCbus_Thermal_LS (R44.1)
V_DCBus: JOLT_21732_Driver_Conn (J2.7), JOLT_21732_DCbus_Thermal_LS (C49.1 R36.1)
VCC1: JOLT_21732_Driver_Conn (12 pins), JOLT_21732_OI_AIN_PWM_check (16 pins), JOLT_21732_DCbus_Thermal_LS (8 pins), JOLT_21732_Supply_Bias (C4.1 C5.1 R4.2 U1.8)

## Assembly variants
001: not fitted C15 C16 C36 C37 C86 C97 MD1 R9 R20 R79 R105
